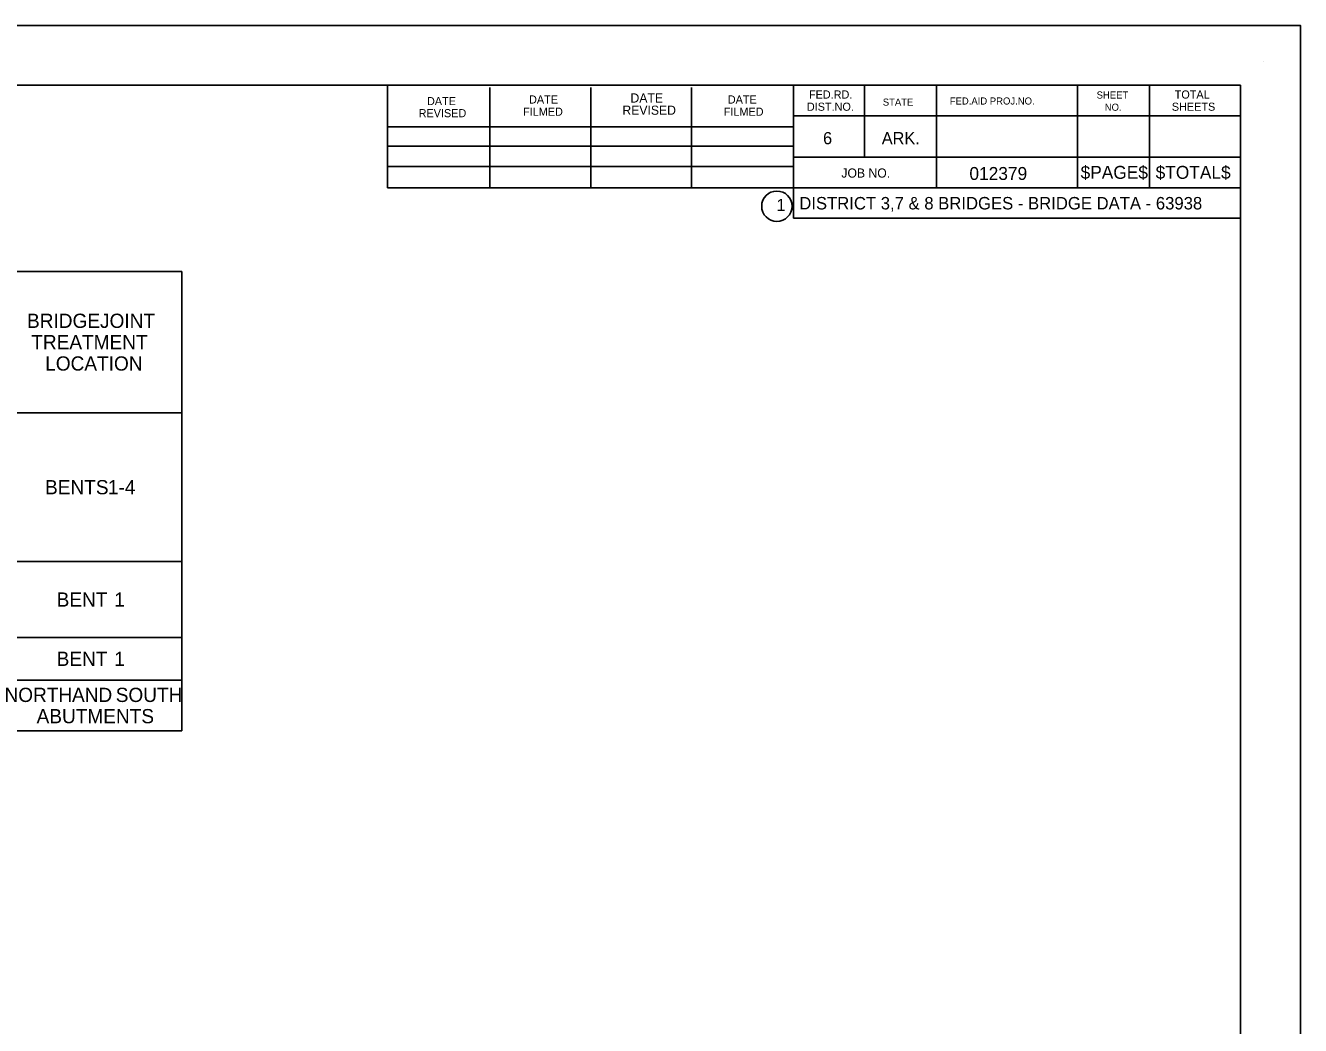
# Model space of a CAD drawing. Extents: x 16 to 1228740, y 11 to 152440.
# Drawn here: x 17.466 to 18.49, y 11.739 to 12.543 of the extents above; entities that cross this region are included whole.
import ezdxf

# ---------------------------------------------------------------- set-up
doc = ezdxf.new("R2010")
doc.units = 0
for name, color, linetype in [('B_Copy In', 7, 'Continuous'), ('B_Text', 7, 'Continuous'), ('R_Border', 7, 'Continuous')]:
    doc.layers.add(name, color=color, linetype=linetype)

msp = doc.modelspace()

# ---------------------------------------------------------------- linework, layer by layer
at = {"layer": 'B_Text'}
for p, q in [((16.103, 12.3452), (17.5915, 12.3452)), ((17.5915, 11.9761), (17.5915, 12.3452)), ((16.103, 12.2316), (17.5915, 12.2316)), ((16.103, 12.112), (17.5915, 12.112)), ((16.103, 12.0511), (17.5915, 12.0511)), ((16.103, 12.0167), (17.5915, 12.0167)), ((16.103, 11.9761), (17.5915, 11.9761))]:
    msp.add_line(p, q, dxfattribs=at)
at = {"layer": 'R_Border'}
for p, q in [((18.4604, 12.514), (18.4604, 12.514)), ((15.7833, 12.4948), (18.4422, 12.4948)), ((17.7567, 12.4124), (17.7567, 12.4948)), ((17.8389, 12.4124), (17.8389, 12.4931)), ((17.9202, 12.4124), (17.9202, 12.4931)), ((18.0009, 12.4124), (18.0009, 12.4931)), ((18.083, 12.4948), (18.083, 12.3881)), ((18.14, 12.4948), (18.14, 12.4369)), ((18.1979, 12.4948), (18.1979, 12.4124)), ((18.311, 12.4948), (18.311, 12.4124)), ((18.3689, 12.4948), (18.3689, 12.4124)), ((18.4422, 10.7576), (18.4422, 12.4948)), ((18.4422, 12.4703), (18.083, 12.4703)), ((18.4422, 12.4704), (18.4422, 12.4704)), ((17.7567, 12.4613), (18.083, 12.4613)), ((17.7567, 12.4458), (18.083, 12.4458)), ((18.4422, 12.4369), (18.083, 12.4369)), ((18.1077, 12.4369), (18.4422, 12.4369)), ((17.7567, 12.4124), (17.7567, 12.4296)), ((17.7567, 12.4296), (18.083, 12.4296)), ((18.4422, 12.4124), (17.7567, 12.4124)), ((18.083, 12.3881), (18.4422, 12.3881)), ((18.083, 12.3881), (18.4422, 12.3881))]:
    msp.add_line(p, q, dxfattribs=at)
msp.add_lwpolyline([(15.6569, 12.5428), (18.4903, 12.5428), (18.4903, 10.7095), (15.6569, 10.7095)], close=True, dxfattribs=at)
msp.add_circle((18.0696, 12.3976), 0.0122, dxfattribs=at)

# ---------------------------------------------------------------- texts
at = {"layer": 'B_Copy In'}
msp.add_text('DISTRICT 3,7 & 8 BRIDGES - BRIDGE DATA - 63938', height=0.010014, dxfattribs=at).set_placement((18.0876, 12.395))
at = {"layer": 'B_Text'}
for s, p in [('BRIDGE', (17.4672, 12.2998)), (' JOINT', (17.5216, 12.2998)), ('TREATMENT', (17.4706, 12.2827)), ('LOCATION', (17.4818, 12.2655)), ('BENTS', (17.4817, 12.1661)), (' 1-4', (17.5279, 12.1661)), ('BENT', (17.491, 12.0758)), ('  1', (17.5288, 12.0758)), ('BENT', (17.491, 12.0282)), ('  1', (17.5288, 12.0282)), ('NORTH', (17.4491, 11.9992)), (' AND', (17.4991, 11.9992)), (' SOUTH', (17.5342, 11.9992)), ('ABUTMENTS', (17.4749, 11.9821))]:
    msp.add_text(s, height=0.01144, dxfattribs=at).set_placement(p)
at = {"layer": 'R_Border'}
for s, height, p in [('DATE', 0.00652, (17.8705, 12.4801)), ('DATE', 0.00733, (17.952, 12.4809)), ('DATE', 0.00652, (18.0302, 12.4801)), ('FED.RD.', 0.00652, (18.0954, 12.4841)), ('SHEET', 0.0057, (18.3265, 12.4841)), ('TOTAL', 0.00652, (18.3892, 12.4841)), ('DATE', 0.00652, (17.7885, 12.4788)), ('FILMED', 0.00652, (17.8657, 12.4703)), ('REVISED', 0.00733, (17.9455, 12.4711)), ('FILMED', 0.00652, (18.0269, 12.4703)), ('DIST.NO.', 0.00652, (18.0937, 12.4743)), ('STATE', 0.0057, (18.1547, 12.4784)), ('FED.AID PROJ.NO.', 0.0057, (18.2085, 12.4793)), ('NO.', 0.0057, (18.333, 12.4743)), ('SHEETS', 0.00652, (18.3869, 12.4743)), ('REVISED', 0.00652, (17.7818, 12.4691)), ('6', 0.00977, (18.1067, 12.4474)), ('ARK.', 0.00977, (18.1539, 12.4474)), ('JOB NO.', 0.00733, (18.1214, 12.4206)), ('012379', 0.0104, (18.2243, 12.4187)), ('$PAGE$', 0.0104, (18.3136, 12.4196)), ('$TOTAL$', 0.0104, (18.3739, 12.4196)), ('1', 0.00977, (18.0693, 12.3937))]:
    msp.add_text(s, height=height, dxfattribs=at).set_placement(p)

doc.saveas('drawing.dxf')
